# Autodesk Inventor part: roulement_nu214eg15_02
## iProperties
Shininess: 64.0
Length Units: 11269
Angle Units: 11279
Time Units: 11290
Mass Units: 11283
Length Display Precision: 3
Angle Display Precision: 2
Compacted: True
Part Number: roulement_nu214eg15_02
Document SubType Name: Modeling
Created: 2005-02
Material: Par défaut
Designer: LEGERET Philippe
Density: 0.0
Volumn: 0.0
Area: 0.0
PropertySet Name: Model Information
Control State: 0
Master: False
Checked Out: False
Author: LEGERET Philippe
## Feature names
1. Base1
